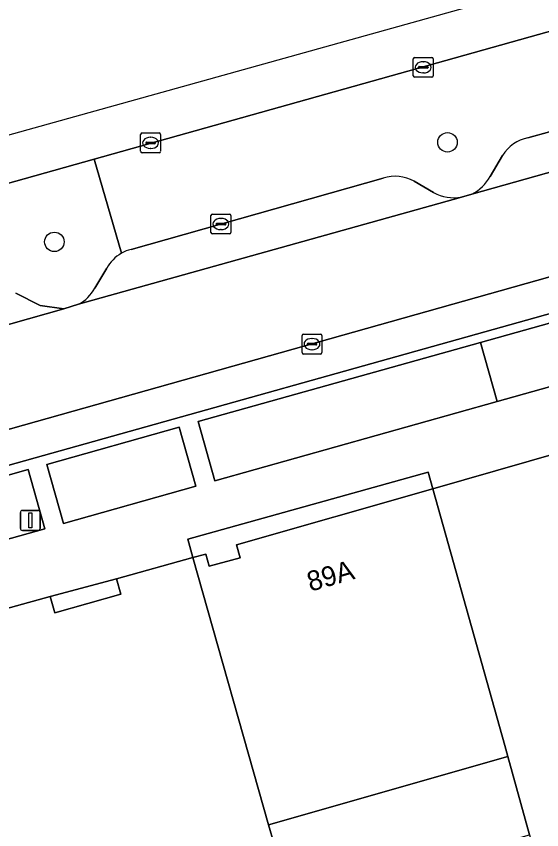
# Model space of a CAD drawing. Extents: x 159680 to 160786, y 387323 to 388340.
# Drawn here: x 159915.68 to 159942.1, y 388203.42 to 388244.36 of the extents above; entities that cross this region are included whole.
import ezdxf

# ---------------------------------------------------------------- set-up
doc = ezdxf.new("R2010")
doc.units = 0
for name, color, linetype in [('IMGEO_Berm_groen', 7, 'Continuous'), ('IMGEO_Boom', 7, 'Continuous'), ('IMGEO_Erf', 7, 'Continuous'), ('IMGEO_Groenvoorziening', 7, 'Continuous'), ('IMGEO_Kolk', 7, 'Continuous'), ('IMGEO_Pand', 7, 'Continuous'), ('IMGEO_Pand_nummerreeks', 7, 'Continuous'), ('IMGEO_Pand_overbouw', 7, 'Continuous'), ('IMGEO_Parkeervlak_open', 7, 'Continuous'), ('IMGEO_Rijbaan_lokaal_open', 7, 'Continuous'), ('IMGEO_Rijbaan_regionaal_gesloten', 7, 'Continuous'), ('IMGEO_Verkeersbordpaal', 7, 'Continuous'), ('IMGEO_Voetpad_open', 7, 'Continuous')]:
    doc.layers.add(name, color=color, linetype=linetype)

msp = doc.modelspace()

# ---------------------------------------------------------------- linework, layer by layer
at = {"layer": 'IMGEO_Berm_groen'}
for points in [[(160022.709, 388266.163), (159948.924, 388245.417), (159919.6, 388237.172), (159920.962, 388232.427)], [(159941.402, 388238.234), (159945.748, 388239.45), (159950.261, 388240.714), (159954.649, 388241.944)], [(159939.503, 388236.288), (159940.128, 388237.353)], [(159920.962, 388232.427), (159919.6, 388237.172), (159716.247, 388179.993)], [(159921.449, 388232.625), (159934.124, 388236.216)], [(159935.689, 388236.053), (159936.661, 388235.487)], [(159938.057, 388235.259), (159938.589, 388235.41)], [(159919.629, 388230.668), (159920.231, 388231.676)], [(159915.662, 388230.417), (159916.877, 388229.798), (159918.074, 388229.639), (159918.811, 388229.861)]]:
    msp.add_lwpolyline(points, dxfattribs=at)
for centre, radius, start, end in [((159941.752, 388236.366), 1.901, 100.6232, 148.7063), ((159934.715, 388234.295), 2.01, 61.0135, 107.0942), ((159937.611, 388237.343), 2.166, 296.8394, 330.8589), ((159937.687, 388237.379), 2.152, 241.5403, 279.908), ((159921.921, 388230.762), 1.921, 119.9449, 151.6014), ((159921.917, 388230.776), 1.908, 104.2052, 120.0452), ((159917.817, 388231.687), 2.079, 298.5695, 330.6549)]:
    msp.add_arc(centre, radius, start, end, dxfattribs=at)
at = {"layer": 'IMGEO_Boom'}
for centre in [(159937.36, 388238.014), (159917.595, 388233.003)]:
    msp.add_circle(centre, 0.489, dxfattribs=at)
at = {"layer": 'IMGEO_Erf'}
msp.add_lwpolyline([(159940.393, 388207.1), (159928.356, 388203.671), (159929.499, 388199.78), (159929.781, 388199.86), (159941.49, 388203.168)], close=True, dxfattribs=at)
at = {"layer": 'IMGEO_Groenvoorziening'}
for points in [[(159939.021, 388227.946), (159924.821, 388223.967), (159925.664, 388220.973), (159939.859, 388224.967)], [(159924.705, 388220.707), (159923.868, 388223.676), (159917.222, 388221.801), (159918.058, 388218.833)], [(159901.377, 388214.136), (159911.233, 388216.913), (159917.12, 388218.569), (159916.281, 388221.546), (159911.88, 388220.302), (159911.625, 388220.23), (159910.631, 388220.491), (159907.701, 388219.666), (159907.042, 388218.919), (159906.925, 388218.886), (159900.55, 388217.071)]]:
    msp.add_lwpolyline(points, close=True, dxfattribs=at)
at = {"layer": 'IMGEO_Kolk'}
for p, q in [((159935.64, 388241.362), (159935.64, 388242.214)), ((159935.715, 388242.288), (159936.567, 388242.288)), ((159936.641, 388242.214), (159936.641, 388241.362)), ((159935.899, 388241.782), (159935.899, 388241.794)), ((159935.942, 388241.831), (159936.34, 388241.831)), ((159936.128, 388242.068), (159936.153, 388242.068)), ((159936.383, 388241.794), (159936.383, 388241.782)), ((159936.337, 388241.745), (159935.939, 388241.745)), ((159936.151, 388241.508), (159936.126, 388241.508)), ((159936.567, 388241.288), (159935.715, 388241.288)), ((159922.007, 388238.485), (159922.859, 388238.485)), ((159921.932, 388237.559), (159921.932, 388238.411)), ((159922.42, 388238.265), (159922.445, 388238.265)), ((159922.933, 388238.411), (159922.933, 388237.559)), ((159922.191, 388237.979), (159922.191, 388237.991)), ((159922.629, 388237.942), (159922.231, 388237.942)), ((159922.234, 388238.028), (159922.632, 388238.028)), ((159922.443, 388237.705), (159922.418, 388237.705)), ((159922.675, 388237.991), (159922.675, 388237.979)), ((159922.859, 388237.485), (159922.007, 388237.485)), ((159925.543, 388234.402), (159926.395, 388234.402)), ((159925.468, 388233.476), (159925.468, 388234.328)), ((159925.956, 388234.182), (159925.981, 388234.182)), ((159926.469, 388234.328), (159926.469, 388233.476)), ((159925.727, 388233.896), (159925.727, 388233.908)), ((159926.165, 388233.859), (159925.767, 388233.859)), ((159925.77, 388233.945), (159926.168, 388233.945)), ((159925.979, 388233.622), (159925.954, 388233.622)), ((159926.211, 388233.908), (159926.211, 388233.896)), ((159926.395, 388233.402), (159925.543, 388233.402)), ((159930.047, 388227.431), (159930.047, 388228.283)), ((159930.122, 388228.357), (159930.974, 388228.357)), ((159931.048, 388228.283), (159931.048, 388227.431)), ((159930.306, 388227.851), (159930.306, 388227.863)), ((159930.349, 388227.9), (159930.747, 388227.9)), ((159930.535, 388228.137), (159930.56, 388228.137)), ((159930.79, 388227.863), (159930.79, 388227.851)), ((159930.744, 388227.814), (159930.346, 388227.814)), ((159930.558, 388227.577), (159930.533, 388227.577)), ((159930.974, 388227.357), (159930.122, 388227.357))]:
    msp.add_line(p, q, dxfattribs=at)
for points in [[(159935.64, 388241.362), (159935.64, 388242.214)], [(159935.715, 388242.288), (159936.567, 388242.288)], [(159936.641, 388242.214), (159936.641, 388241.362)], [(159936.567, 388241.288), (159935.715, 388241.288)], [(159922.007, 388238.485), (159922.859, 388238.485)], [(159921.932, 388237.559), (159921.932, 388238.411)], [(159922.933, 388238.411), (159922.933, 388237.559)], [(159922.859, 388237.485), (159922.007, 388237.485)], [(159925.543, 388234.402), (159926.395, 388234.402)], [(159925.468, 388233.476), (159925.468, 388234.328)], [(159926.469, 388234.328), (159926.469, 388233.476)], [(159926.395, 388233.402), (159925.543, 388233.402)], [(159930.047, 388227.431), (159930.047, 388228.283)], [(159930.122, 388228.357), (159930.974, 388228.357)], [(159931.048, 388228.283), (159931.048, 388227.431)], [(159930.974, 388227.357), (159930.122, 388227.357)]]:
    msp.add_lwpolyline(points, dxfattribs=at)
for centre, radius, start, end in [((159935.717, 388242.212), 0.0765, 91.552, 178.448), ((159935.717, 388242.212), 0.0765, 91.552, 178.448), ((159936.565, 388242.212), 0.0765, 1.552, 88.448), ((159936.565, 388242.212), 0.0765, 1.552, 88.448), ((159935.939, 388241.791), 0.0403, 85.8775, 175.7526), ((159935.936, 388241.781), 0.0366, 178.938, 274.7102), ((159936.34, 388241.788), 0.043, 264.8664, 352.4533), ((159936.344, 388241.793), 0.0386, 1.7309, 96.639), ((159935.717, 388241.364), 0.0765, 181.552, 268.448), ((159935.717, 388241.364), 0.0765, 181.552, 268.448), ((159936.565, 388241.364), 0.0765, 271.552, 358.448), ((159936.565, 388241.364), 0.0765, 271.552, 358.448), ((159922.009, 388238.409), 0.0765, 91.552, 178.448), ((159922.009, 388238.409), 0.0765, 91.552, 178.448), ((159922.857, 388238.409), 0.0765, 1.552, 88.448), ((159922.857, 388238.409), 0.0765, 1.552, 88.448), ((159922.231, 388237.988), 0.0403, 85.8775, 175.7526), ((159922.228, 388237.978), 0.0366, 178.938, 274.7102), ((159922.632, 388237.985), 0.043, 264.8664, 352.4533), ((159922.636, 388237.99), 0.0386, 1.7309, 96.639), ((159922.009, 388237.561), 0.0765, 181.552, 268.448), ((159922.009, 388237.561), 0.0765, 181.552, 268.448), ((159922.857, 388237.561), 0.0765, 271.552, 358.448), ((159922.857, 388237.561), 0.0765, 271.552, 358.448), ((159925.545, 388234.326), 0.0765, 91.552, 178.448), ((159925.545, 388234.326), 0.0765, 91.552, 178.448), ((159926.393, 388234.326), 0.0765, 1.552, 88.448), ((159926.393, 388234.326), 0.0765, 1.552, 88.448), ((159925.767, 388233.905), 0.0403, 85.8775, 175.7526), ((159925.764, 388233.895), 0.0366, 178.938, 274.7102), ((159926.168, 388233.902), 0.043, 264.8664, 352.4533), ((159926.172, 388233.907), 0.0386, 1.7309, 96.639), ((159925.545, 388233.478), 0.0765, 181.552, 268.448), ((159925.545, 388233.478), 0.0765, 181.552, 268.448), ((159926.393, 388233.478), 0.0765, 271.552, 358.448), ((159926.393, 388233.478), 0.0765, 271.552, 358.448), ((159930.124, 388228.281), 0.0765, 91.552, 178.448), ((159930.124, 388228.281), 0.0765, 91.552, 178.448), ((159930.972, 388228.281), 0.0765, 1.552, 88.448), ((159930.972, 388228.281), 0.0765, 1.552, 88.448), ((159930.346, 388227.86), 0.0403, 85.8775, 175.7526), ((159930.343, 388227.85), 0.0366, 178.938, 274.7102), ((159930.747, 388227.857), 0.043, 264.8664, 352.4533), ((159930.751, 388227.862), 0.0386, 1.7309, 96.639), ((159930.124, 388227.433), 0.0765, 181.552, 268.448), ((159930.124, 388227.433), 0.0765, 181.552, 268.448), ((159930.972, 388227.433), 0.0765, 271.552, 358.448), ((159930.972, 388227.433), 0.0765, 271.552, 358.448)]:
    msp.add_arc(centre, radius, start, end, dxfattribs=at)
for centre, major_axis, ratio, start_param, end_param in [((159936.127, 388241.788), (-0.387, 0.002), 0.722429, 4.712389, 7.853982), ((159936.152, 388241.788), (-0.39, 0.002), 0.717154, 1.570796, 4.712389), ((159922.419, 388237.985), (-0.387, 0.002), 0.722429, 4.712389, 7.853982), ((159922.444, 388237.985), (-0.39, 0.002), 0.717154, 1.570796, 4.712389), ((159925.955, 388233.902), (-0.387, 0.002), 0.722429, 4.712389, 7.853982), ((159925.98, 388233.902), (-0.39, 0.002), 0.717154, 1.570796, 4.712389), ((159930.534, 388227.857), (-0.387, 0.002), 0.722429, 4.712389, 7.853982), ((159930.559, 388227.857), (-0.39, 0.002), 0.717154, 1.570796, 4.712389)]:
    msp.add_ellipse(centre, major_axis=major_axis, ratio=ratio, start_param=start_param, end_param=end_param, dxfattribs=at)
at = {"layer": 'IMGEO_Pand'}
for points in [[(159966.388, 388214.227), (159962.495, 388227.995), (159955.575, 388226.013), (159954.634, 388225.743), (159951.665, 388224.892), (159951.029, 388224.71), (159936.622, 388220.583), (159940.238, 388207.656), (159940.393, 388207.1), (159941.49, 388203.168), (159945.924, 388187.271), (159947.285, 388182.459), (159947.404, 388182.493), (159973.293, 388189.814), (159971.932, 388194.626), (159969.283, 388203.991)], [(159928.356, 388203.671), (159940.393, 388207.1), (159940.238, 388207.656), (159936.622, 388220.583), (159926.75, 388217.753), (159926.929, 388217.11), (159925.382, 388216.68), (159925.212, 388217.294), (159924.56, 388217.113)], [(159924.56, 388217.113), (159920.726, 388216.048), (159920.944, 388215.266), (159917.61, 388214.339), (159917.383, 388215.156), (159905.403, 388211.829), (159914.378, 388180.082), (159915.697, 388175.388), (159935.06, 388180.859), (159929.781, 388199.86), (159929.499, 388199.78), (159928.356, 388203.671)]]:
    msp.add_lwpolyline(points, close=True, dxfattribs=at)
at = {"layer": 'IMGEO_Pand_overbouw'}
msp.add_lwpolyline([(159917.383, 388215.156), (159917.61, 388214.339), (159920.944, 388215.266), (159920.726, 388216.048)], close=True, dxfattribs=at)
at = {"layer": 'IMGEO_Parkeervlak_open'}
for points in [[(160038.617, 388258.278), (160009.184, 388250), (160000, 388247.417), (159952.178, 388233.968), (159948.035, 388232.803), (159858.217, 388207.473), (159858.303, 388207.163), (159858.874, 388207.325)], [(159954.649, 388241.944), (159950.261, 388240.714), (159945.748, 388239.45), (159941.402, 388238.234)], [(159938.589, 388235.41), (159950.795, 388238.836), (159958.522, 388241.005)], [(159940.128, 388237.353), (159939.503, 388236.288)], [(159934.124, 388236.216), (159921.449, 388232.625)], [(159936.661, 388235.487), (159935.689, 388236.053)], [(159918.811, 388229.861), (159938.057, 388235.259)], [(159911.774, 388220.768), (159946.592, 388230.541), (159946.829, 388230.64), (159947.198, 388231.025), (159947.612, 388231.765)], [(159920.231, 388231.676), (159919.629, 388230.668)], [(159896.382, 388223.491), (159918.074, 388229.639), (159916.877, 388229.798), (159915.662, 388230.417)]]:
    msp.add_lwpolyline(points, dxfattribs=at)
for centre, radius, start, end in [((159941.752, 388236.366), 1.901, 100.6232, 148.7063), ((159934.715, 388234.295), 2.01, 61.0135, 107.0942), ((159937.611, 388237.343), 2.166, 296.8394, 330.8589), ((159937.687, 388237.379), 2.152, 241.5403, 279.908), ((159921.921, 388230.762), 1.921, 119.9449, 151.6014), ((159921.917, 388230.776), 1.908, 104.2052, 120.0452), ((159917.817, 388231.687), 2.079, 298.5695, 330.6549)]:
    msp.add_arc(centre, radius, start, end, dxfattribs=at)
at = {"layer": 'IMGEO_Rijbaan_lokaal_open'}
for points in [[(159990.313, 388250), (159958.999, 388241.151), (159958.522, 388241.005), (159950.795, 388238.836), (159938.589, 388235.41), (159938.057, 388235.259), (159918.811, 388229.861), (159918.074, 388229.639), (159896.382, 388223.491), (159895.708, 388223.298), (159752.279, 388182.917), (159750.225, 388182.349), (159750.033, 388182.294), (159740.394, 388179.542), (159738.197, 388178.962), (159726.603, 388175.761), (159726.396, 388175.68), (159725.585, 388175.389)], [(159723.456, 388169.745), (159723.633, 388169.719), (159724.653, 388169.975), (159726.472, 388170.472), (159748.553, 388176.646), (159753.855, 388178.128), (159770.727, 388182.846), (159773.651, 388183.666), (159779.983, 388185.443), (159808.558, 388193.46), (159829.06, 388199.251), (159853.995, 388206.283), (159858.217, 388207.473), (159948.035, 388232.803)]]:
    msp.add_lwpolyline(points, dxfattribs=at)
at = {"layer": 'IMGEO_Rijbaan_regionaal_gesloten'}
msp.add_lwpolyline([(159702.179, 388176.035), (159702.945, 388176.248), (159704.075, 388176.561), (159705.928, 388177.01), (159716.247, 388179.993), (159919.6, 388237.172), (159948.924, 388245.417), (160022.709, 388266.163), (160022.114, 388268.189), (159861.579, 388223.398), (159698.928, 388178.017)], dxfattribs=at)
at = {"layer": 'IMGEO_Verkeersbordpaal'}
for p, q in [((159915.885, 388218.584), (159915.885, 388219.384)), ((159915.885, 388219.384), (159915.885, 388218.584)), ((159915.985, 388219.484), (159916.775, 388219.484)), ((159916.775, 388219.484), (159915.985, 388219.484)), ((159916.875, 388219.384), (159916.875, 388218.584)), ((159916.875, 388218.584), (159916.875, 388219.384)), ((159916.775, 388218.484), (159915.985, 388218.484)), ((159915.985, 388218.484), (159916.775, 388218.484))]:
    msp.add_line(p, q, dxfattribs=at)
msp.add_lwpolyline([(159916.305, 388219.359), (159916.455, 388219.359), (159916.455, 388218.609), (159916.305, 388218.609), (159916.305, 388219.359)], dxfattribs=at)
for centre, start, end in [((159915.985, 388219.384), 90, 180), ((159915.985, 388219.384), 90, 180), ((159916.775, 388219.384), 0, 90), ((159916.775, 388219.384), 360, 90), ((159915.985, 388218.584), 180, 270), ((159915.985, 388218.584), 180, 270), ((159916.775, 388218.584), 270, 0), ((159916.775, 388218.584), 270, 0)]:
    msp.add_arc(centre, 0.1, start, end, dxfattribs=at)
at = {"layer": 'IMGEO_Voetpad_open'}
for points in [[(159905.403, 388211.829), (159917.383, 388215.156), (159920.726, 388216.048), (159924.56, 388217.113), (159924.3, 388218.048), (159936.392, 388221.407), (159936.622, 388220.583), (159951.029, 388224.71), (159950.686, 388225.927), (159951.324, 388226.107), (159954.294, 388226.947), (159954.634, 388225.743), (159955.575, 388226.013), (159962.495, 388227.995), (159963.353, 388228.241), (159995.562, 388237.47)], [(159953.361, 388229.839), (159952.787, 388231.833), (159952.545, 388232.675), (159949.671, 388231.871), (159949.923, 388231), (159950.781, 388228.04), (159946.49, 388226.833), (159939.859, 388224.967), (159925.664, 388220.973), (159924.821, 388223.967), (159939.021, 388227.946), (159945.654, 388229.804), (159946.927, 388230.161), (159946.829, 388230.64), (159946.592, 388230.541), (159911.774, 388220.768)], [(159911.88, 388220.302), (159916.281, 388221.546), (159917.12, 388218.569), (159911.233, 388216.913)]]:
    msp.add_lwpolyline(points, dxfattribs=at)
for points in [[(159945.654, 388229.804), (159939.021, 388227.946), (159939.859, 388224.967), (159946.49, 388226.833)], [(159924.705, 388220.707), (159918.058, 388218.833), (159917.222, 388221.801), (159923.868, 388223.676)], [(159925.212, 388217.294), (159925.382, 388216.68), (159926.929, 388217.11), (159926.75, 388217.753), (159936.622, 388220.583), (159936.392, 388221.407), (159924.3, 388218.048), (159924.56, 388217.113)], [(159917.383, 388215.156), (159917.61, 388214.339), (159920.944, 388215.266), (159920.726, 388216.048)]]:
    msp.add_lwpolyline(points, close=True, dxfattribs=at)

# ---------------------------------------------------------------- texts
at = {"layer": 'IMGEO_Pand_nummerreeks'}
msp.add_text('89A', height=1, rotation=16.0745, dxfattribs=at).set_placement((159930.468, 388215.395))

doc.saveas('drawing.dxf')
